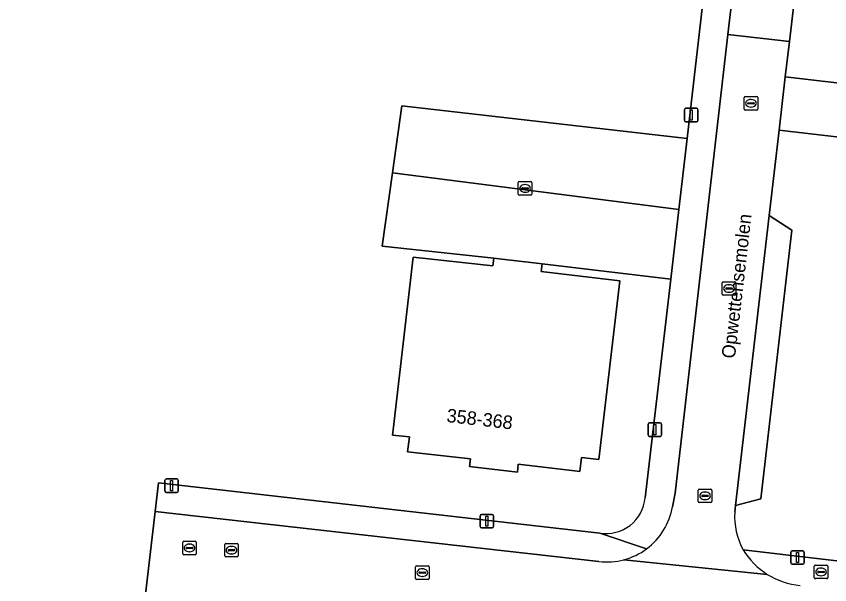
# Model space of a CAD drawing. Extents: x 161241 to 161758, y 384138 to 384885.
# Drawn here: x 161339.7 to 161399.9, y 384579.4 to 384621.5 of the extents above; entities that cross this region are included whole.
import ezdxf

# ---------------------------------------------------------------- set-up
doc = ezdxf.new("R2010")
doc.units = 0
for name, color, linetype in [('IMGEO_Brandkraan', 7, 'Continuous'), ('IMGEO_Erf', 7, 'Continuous'), ('IMGEO_Kolk', 7, 'Continuous'), ('IMGEO_Lichtmast', 7, 'Continuous'), ('IMGEO_Openbare_ruimte_label', 7, 'Continuous'), ('IMGEO_Pand', 7, 'Continuous'), ('IMGEO_Pand_nummerreeks', 7, 'Continuous'), ('IMGEO_Parkeervlak_open', 7, 'Continuous'), ('IMGEO_Rijbaan_lokaal_open', 7, 'Continuous'), ('IMGEO_Rioolput', 7, 'Continuous'), ('IMGEO_Voetpad_open', 7, 'Continuous')]:
    doc.layers.add(name, color=color, linetype=linetype)

msp = doc.modelspace()

# ---------------------------------------------------------------- linework, layer by layer
at = {"layer": 'IMGEO_Brandkraan'}
for p, q in [((161398.807, 384579.905), (161398.807, 384580.757)), ((161398.882, 384580.831), (161399.734, 384580.831)), ((161399.295, 384580.611), (161399.32, 384580.611)), ((161399.808, 384580.757), (161399.808, 384579.905)), ((161399.066, 384580.325), (161399.066, 384580.337)), ((161399.504, 384580.288), (161399.106, 384580.288)), ((161399.109, 384580.374), (161399.507, 384580.374)), ((161399.318, 384580.051), (161399.293, 384580.051)), ((161399.55, 384580.337), (161399.55, 384580.325)), ((161399.734, 384579.831), (161398.882, 384579.831))]:
    msp.add_line(p, q, dxfattribs=at)
for points in [[(161398.807, 384579.905), (161398.807, 384580.757)], [(161398.882, 384580.831), (161399.734, 384580.831)], [(161399.808, 384580.757), (161399.808, 384579.905)], [(161399.734, 384579.831), (161398.882, 384579.831)]]:
    msp.add_lwpolyline(points, dxfattribs=at)
for centre, radius, start, end in [((161398.884, 384580.755), 0.0765, 91.55205, 178.44795), ((161398.884, 384580.755), 0.0765, 91.55205, 178.44795), ((161399.732, 384580.755), 0.0765, 1.55205, 88.44795), ((161399.732, 384580.755), 0.0765, 1.55205, 88.44795), ((161399.106, 384580.334), 0.0403, 85.87752, 175.75265), ((161399.103, 384580.324), 0.0366, 178.93798, 274.71019), ((161399.507, 384580.331), 0.043, 264.86636, 352.45326), ((161399.511, 384580.336), 0.0386, 1.73085, 96.63898), ((161398.884, 384579.907), 0.0765, 181.55205, 268.44795), ((161398.884, 384579.907), 0.0765, 181.55205, 268.44795), ((161399.732, 384579.907), 0.0765, 271.55205, 358.44795), ((161399.732, 384579.907), 0.0765, 271.55205, 358.44795)]:
    msp.add_arc(centre, radius, start, end, dxfattribs=at)
for centre, major_axis, ratio, start_param, end_param in [((161399.294, 384580.331), (-0.387, 0.002), 0.722429, 4.712389, 7.853982), ((161399.319, 384580.331), (-0.39, 0.002), 0.717154, 1.570796, 4.712389)]:
    msp.add_ellipse(centre, major_axis=major_axis, ratio=ratio, start_param=start_param, end_param=end_param, dxfattribs=at)
at = {"layer": 'IMGEO_Erf'}
for points in [[(161458.589, 384639.718), (161400.088, 384646.416), (161397.281, 384622.401), (161396.961, 384619.66), (161396.655, 384617.039), (161425.024, 384613.724), (161425.387, 384616.773), (161427.698, 384616.498), (161427.335, 384613.449), (161436.939, 384612.308), (161436.503, 384609.048), (161435.624, 384602.469), (161435.067, 384598.3), (161434.079, 384598.432), (161434.571, 384602.594), (161430.726, 384603.048), (161431.421, 384608.981), (161396.194, 384613.099), (161395.453, 384606.759), (161397.13, 384605.671), (161394.834, 384585.76), (161392.961, 384585.251), (161392.905, 384584.764)], [(161386.264, 384585.815), (161388.17, 384602.03), (161378.63, 384603.18), (161378.553, 384602.616), (161384.384, 384601.913), (161382.88, 384589.077), (161382.832, 384588.671), (161381.561, 384588.828), (161381.438, 384587.782), (161381.025, 384587.83), (161376.862, 384588.317), (161376.812, 384587.738), (161373.26, 384588.138), (161373.333, 384588.711), (161369.092, 384589.195), (161368.661, 384589.244), (161368.811, 384590.339), (161367.545, 384590.466), (161367.592, 384590.876), (161369.069, 384603.683), (161374.991, 384603.033), (161375.048, 384603.608), (161366.788, 384604.482), (161367.54, 384609.919), (161368.227, 384614.894), (161389.377, 384612.476), (161392.602, 384640.347)], [(161332.131, 384432.245), (161332.897, 384438.907), (161336.632, 384471.394), (161336.946, 384474.139), (161340.403, 384504.377), (161340.647, 384506.515), (161340.82, 384506.489), (161349.943, 384584.816), (161350.191, 384586.943), (161382.92, 384583.217)], [(161393.526, 384581.977), (161448.824, 384575.465)]]:
    msp.add_lwpolyline(points, dxfattribs=at)
for centre, radius, start, end in [((161383.388, 384586.066), 2.887, 260.67579, 355.01247), ((161398.109, 384584.461), 5.213, 176.66706, 208.45585)]:
    msp.add_arc(centre, radius, start, end, dxfattribs=at)
at = {"layer": 'IMGEO_Kolk'}
for p, q in [((161393.684, 384615.584), (161394.536, 384615.584)), ((161393.609, 384614.658), (161393.609, 384615.51)), ((161393.868, 384615.078), (161393.868, 384615.09)), ((161394.306, 384615.041), (161393.908, 384615.041)), ((161393.911, 384615.127), (161394.309, 384615.127)), ((161394.097, 384615.364), (161394.122, 384615.364)), ((161394.352, 384615.09), (161394.352, 384615.078)), ((161394.61, 384615.51), (161394.61, 384614.658)), ((161394.536, 384614.584), (161393.684, 384614.584)), ((161394.12, 384614.804), (161394.095, 384614.804)), ((161376.869, 384608.348), (161376.869, 384609.2)), ((161376.944, 384609.274), (161377.796, 384609.274)), ((161377.357, 384609.054), (161377.382, 384609.054)), ((161377.87, 384609.2), (161377.87, 384608.348)), ((161377.128, 384608.768), (161377.128, 384608.78)), ((161377.566, 384608.731), (161377.168, 384608.731)), ((161377.171, 384608.817), (161377.569, 384608.817)), ((161377.38, 384608.494), (161377.355, 384608.494)), ((161377.612, 384608.78), (161377.612, 384608.768)), ((161377.796, 384608.274), (161376.944, 384608.274)), ((161391.987, 384600.926), (161391.987, 384601.778)), ((161392.062, 384601.852), (161392.914, 384601.852)), ((161392.988, 384601.778), (161392.988, 384600.926)), ((161392.246, 384601.346), (161392.246, 384601.358)), ((161392.684, 384601.309), (161392.286, 384601.309)), ((161392.289, 384601.395), (161392.687, 384601.395)), ((161392.475, 384601.632), (161392.5, 384601.632)), ((161392.73, 384601.358), (161392.73, 384601.346)), ((161392.914, 384600.852), (161392.062, 384600.852)), ((161392.498, 384601.072), (161392.473, 384601.072)), ((161390.209, 384585.55), (161390.209, 384586.402)), ((161390.284, 384586.476), (161391.136, 384586.476)), ((161390.697, 384586.256), (161390.722, 384586.256)), ((161391.21, 384586.402), (161391.21, 384585.55)), ((161391.136, 384585.476), (161390.284, 384585.476)), ((161390.468, 384585.97), (161390.468, 384585.982)), ((161390.906, 384585.933), (161390.508, 384585.933)), ((161390.511, 384586.019), (161390.909, 384586.019)), ((161390.72, 384585.696), (161390.695, 384585.696)), ((161390.952, 384585.982), (161390.952, 384585.97)), ((161355.187, 384582.444), (161356.039, 384582.444)), ((161355.112, 384581.518), (161355.112, 384582.37)), ((161355.371, 384581.938), (161355.371, 384581.95)), ((161355.809, 384581.901), (161355.411, 384581.901)), ((161355.414, 384581.987), (161355.812, 384581.987)), ((161355.6, 384582.224), (161355.625, 384582.224)), ((161355.855, 384581.95), (161355.855, 384581.938)), ((161356.113, 384582.37), (161356.113, 384581.518)), ((161356.039, 384581.444), (161355.187, 384581.444)), ((161355.623, 384581.664), (161355.598, 384581.664)), ((161369.257, 384579.854), (161369.257, 384580.706)), ((161369.332, 384580.78), (161370.184, 384580.78)), ((161370.258, 384580.706), (161370.258, 384579.854)), ((161369.516, 384580.274), (161369.516, 384580.286)), ((161369.954, 384580.237), (161369.556, 384580.237)), ((161369.559, 384580.323), (161369.957, 384580.323)), ((161369.768, 384580), (161369.743, 384580)), ((161369.745, 384580.56), (161369.77, 384580.56)), ((161370, 384580.286), (161370, 384580.274)), ((161370.184, 384579.78), (161369.332, 384579.78))]:
    msp.add_line(p, q, dxfattribs=at)
for points in [[(161393.684, 384615.584), (161394.536, 384615.584)], [(161393.609, 384614.658), (161393.609, 384615.51)], [(161394.61, 384615.51), (161394.61, 384614.658)], [(161394.536, 384614.584), (161393.684, 384614.584)], [(161376.869, 384608.348), (161376.869, 384609.2)], [(161376.944, 384609.274), (161377.796, 384609.274)], [(161377.87, 384609.2), (161377.87, 384608.348)], [(161377.796, 384608.274), (161376.944, 384608.274)], [(161391.987, 384600.926), (161391.987, 384601.778)], [(161392.062, 384601.852), (161392.914, 384601.852)], [(161392.988, 384601.778), (161392.988, 384600.926)], [(161392.914, 384600.852), (161392.062, 384600.852)], [(161390.209, 384585.55), (161390.209, 384586.402)], [(161390.284, 384586.476), (161391.136, 384586.476)], [(161391.21, 384586.402), (161391.21, 384585.55)], [(161391.136, 384585.476), (161390.284, 384585.476)], [(161355.187, 384582.444), (161356.039, 384582.444)], [(161355.112, 384581.518), (161355.112, 384582.37)], [(161356.113, 384582.37), (161356.113, 384581.518)], [(161356.039, 384581.444), (161355.187, 384581.444)], [(161369.257, 384579.854), (161369.257, 384580.706)], [(161369.332, 384580.78), (161370.184, 384580.78)], [(161370.258, 384580.706), (161370.258, 384579.854)], [(161370.184, 384579.78), (161369.332, 384579.78)]]:
    msp.add_lwpolyline(points, dxfattribs=at)
for centre, radius, start, end in [((161393.686, 384615.508), 0.0765, 91.55205, 178.44795), ((161393.686, 384615.508), 0.0765, 91.55205, 178.44795), ((161394.534, 384615.508), 0.0765, 1.55205, 88.44795), ((161394.534, 384615.508), 0.0765, 1.55205, 88.44795), ((161393.908, 384615.087), 0.0403, 85.87752, 175.75265), ((161393.905, 384615.077), 0.0366, 178.93798, 274.71019), ((161394.309, 384615.084), 0.043, 264.86636, 352.45326), ((161394.313, 384615.089), 0.0386, 1.73085, 96.63898), ((161393.686, 384614.66), 0.0765, 181.55205, 268.44795), ((161393.686, 384614.66), 0.0765, 181.55205, 268.44795), ((161394.534, 384614.66), 0.0765, 271.55205, 358.44795), ((161394.534, 384614.66), 0.0765, 271.55205, 358.44795), ((161376.946, 384609.198), 0.0765, 91.55205, 178.44795), ((161376.946, 384609.198), 0.0765, 91.55205, 178.44795), ((161377.794, 384609.198), 0.0765, 1.55205, 88.44795), ((161377.794, 384609.198), 0.0765, 1.55205, 88.44795), ((161376.946, 384608.35), 0.0765, 181.55205, 268.44795), ((161376.946, 384608.35), 0.0765, 181.55205, 268.44795), ((161377.168, 384608.777), 0.0403, 85.87752, 175.75265), ((161377.165, 384608.767), 0.0366, 178.93798, 274.71019), ((161377.569, 384608.774), 0.043, 264.86636, 352.45326), ((161377.573, 384608.779), 0.0386, 1.73085, 96.63898), ((161377.794, 384608.35), 0.0765, 271.55205, 358.44795), ((161377.794, 384608.35), 0.0765, 271.55205, 358.44795), ((161392.064, 384601.776), 0.0765, 91.55205, 178.44795), ((161392.064, 384601.776), 0.0765, 91.55205, 178.44795), ((161392.912, 384601.776), 0.0765, 1.55205, 88.44795), ((161392.912, 384601.776), 0.0765, 1.55205, 88.44795), ((161392.286, 384601.355), 0.0403, 85.87752, 175.75265), ((161392.283, 384601.345), 0.0366, 178.93798, 274.71019), ((161392.687, 384601.352), 0.043, 264.86636, 352.45326), ((161392.691, 384601.357), 0.0386, 1.73085, 96.63898), ((161392.064, 384600.928), 0.0765, 181.55205, 268.44795), ((161392.064, 384600.928), 0.0765, 181.55205, 268.44795), ((161392.912, 384600.928), 0.0765, 271.55205, 358.44795), ((161392.912, 384600.928), 0.0765, 271.55205, 358.44795), ((161390.286, 384586.4), 0.0765, 91.55205, 178.44795), ((161390.286, 384586.4), 0.0765, 91.55205, 178.44795), ((161391.134, 384586.4), 0.0765, 1.55205, 88.44795), ((161391.134, 384586.4), 0.0765, 1.55205, 88.44795), ((161390.286, 384585.552), 0.0765, 181.55205, 268.44795), ((161390.286, 384585.552), 0.0765, 181.55205, 268.44795), ((161390.508, 384585.979), 0.0403, 85.87752, 175.75265), ((161390.505, 384585.969), 0.0366, 178.93798, 274.71019), ((161390.909, 384585.976), 0.043, 264.86636, 352.45326), ((161390.913, 384585.981), 0.0386, 1.73085, 96.63898), ((161391.134, 384585.552), 0.0765, 271.55205, 358.44795), ((161391.134, 384585.552), 0.0765, 271.55205, 358.44795), ((161355.189, 384582.368), 0.0765, 91.55205, 178.44795), ((161355.189, 384582.368), 0.0765, 91.55205, 178.44795), ((161356.037, 384582.368), 0.0765, 1.55205, 88.44795), ((161356.037, 384582.368), 0.0765, 1.55205, 88.44795), ((161355.411, 384581.947), 0.0403, 85.87752, 175.75265), ((161355.408, 384581.937), 0.0366, 178.93798, 274.71019), ((161355.812, 384581.944), 0.043, 264.86636, 352.45326), ((161355.816, 384581.949), 0.0386, 1.73085, 96.63898), ((161355.189, 384581.52), 0.0765, 181.55205, 268.44795), ((161355.189, 384581.52), 0.0765, 181.55205, 268.44795), ((161356.037, 384581.52), 0.0765, 271.55205, 358.44795), ((161356.037, 384581.52), 0.0765, 271.55205, 358.44795), ((161369.334, 384580.704), 0.0765, 91.55205, 178.44795), ((161369.334, 384580.704), 0.0765, 91.55205, 178.44795), ((161370.182, 384580.704), 0.0765, 1.55205, 88.44795), ((161370.182, 384580.704), 0.0765, 1.55205, 88.44795), ((161369.556, 384580.283), 0.0403, 85.87752, 175.75265), ((161369.553, 384580.273), 0.0366, 178.93798, 274.71019), ((161369.957, 384580.28), 0.043, 264.86636, 352.45326), ((161369.961, 384580.285), 0.0386, 1.73085, 96.63898), ((161369.334, 384579.856), 0.0765, 181.55205, 268.44795), ((161369.334, 384579.856), 0.0765, 181.55205, 268.44795), ((161370.182, 384579.856), 0.0765, 271.55205, 358.44795), ((161370.182, 384579.856), 0.0765, 271.55205, 358.44795)]:
    msp.add_arc(centre, radius, start, end, dxfattribs=at)
for centre, major_axis, ratio, start_param, end_param in [((161394.096, 384615.084), (-0.387, 0.002), 0.722429, 4.712389, 7.853982), ((161394.121, 384615.084), (-0.39, 0.002), 0.717154, 1.570796, 4.712389), ((161377.356, 384608.774), (-0.387, 0.002), 0.722429, 4.712389, 7.853982), ((161377.381, 384608.774), (-0.39, 0.002), 0.717154, 1.570796, 4.712389), ((161392.474, 384601.352), (-0.387, 0.002), 0.722429, 4.712389, 7.853982), ((161392.499, 384601.352), (-0.39, 0.002), 0.717154, 1.570796, 4.712389), ((161390.696, 384585.976), (-0.387, 0.002), 0.722429, 4.712389, 7.853982), ((161390.721, 384585.976), (-0.39, 0.002), 0.717154, 1.570796, 4.712389), ((161355.599, 384581.944), (-0.387, 0.002), 0.722429, 4.712389, 7.853982), ((161355.624, 384581.944), (-0.39, 0.002), 0.717154, 1.570796, 4.712389), ((161369.744, 384580.28), (-0.387, 0.002), 0.722429, 4.712389, 7.853982), ((161369.769, 384580.28), (-0.39, 0.002), 0.717154, 1.570796, 4.712389)]:
    msp.add_ellipse(centre, major_axis=major_axis, ratio=ratio, start_param=start_param, end_param=end_param, dxfattribs=at)
at = {"layer": 'IMGEO_Lichtmast'}
for p, q in [((161389.186, 384613.816), (161389.186, 384614.616)), ((161389.186, 384614.616), (161389.186, 384613.816)), ((161389.286, 384614.716), (161390.076, 384614.716)), ((161390.076, 384614.716), (161389.286, 384614.716)), ((161390.176, 384614.616), (161390.176, 384613.816)), ((161390.176, 384613.816), (161390.176, 384614.616)), ((161390.076, 384613.716), (161389.286, 384613.716)), ((161389.286, 384613.716), (161390.076, 384613.716)), ((161386.486, 384590.483), (161386.486, 384591.283)), ((161386.486, 384591.283), (161386.486, 384590.483)), ((161386.586, 384591.383), (161387.376, 384591.383)), ((161387.376, 384591.383), (161386.586, 384591.383)), ((161387.476, 384591.283), (161387.476, 384590.483)), ((161387.476, 384590.483), (161387.476, 384591.283)), ((161387.376, 384590.383), (161386.586, 384590.383)), ((161386.586, 384590.383), (161387.376, 384590.383)), ((161350.681, 384586.324), (161350.681, 384587.124)), ((161350.681, 384587.124), (161350.681, 384586.324)), ((161350.781, 384587.224), (161351.571, 384587.224)), ((161351.571, 384587.224), (161350.781, 384587.224)), ((161351.671, 384587.124), (161351.671, 384586.324)), ((161351.671, 384586.324), (161351.671, 384587.124)), ((161351.571, 384586.224), (161350.781, 384586.224)), ((161350.781, 384586.224), (161351.571, 384586.224)), ((161374.036, 384583.695), (161374.036, 384584.495)), ((161374.036, 384584.495), (161374.036, 384583.695)), ((161374.136, 384584.595), (161374.926, 384584.595)), ((161374.926, 384584.595), (161374.136, 384584.595)), ((161375.026, 384584.495), (161375.026, 384583.695)), ((161375.026, 384583.695), (161375.026, 384584.495)), ((161374.926, 384583.595), (161374.136, 384583.595)), ((161374.136, 384583.595), (161374.926, 384583.595)), ((161397.159, 384581.903), (161397.949, 384581.903)), ((161397.949, 384581.903), (161397.159, 384581.903)), ((161397.059, 384581.003), (161397.059, 384581.803)), ((161397.059, 384581.803), (161397.059, 384581.003)), ((161398.049, 384581.803), (161398.049, 384581.003)), ((161398.049, 384581.003), (161398.049, 384581.803)), ((161397.949, 384580.903), (161397.159, 384580.903)), ((161397.159, 384580.903), (161397.949, 384580.903))]:
    msp.add_line(p, q, dxfattribs=at)
for points in [[(161389.606, 384614.591), (161389.756, 384614.591), (161389.756, 384613.841), (161389.606, 384613.841), (161389.606, 384614.591)], [(161386.906, 384591.258), (161387.056, 384591.258), (161387.056, 384590.508), (161386.906, 384590.508), (161386.906, 384591.258)], [(161351.101, 384587.099), (161351.251, 384587.099), (161351.251, 384586.349), (161351.101, 384586.349), (161351.101, 384587.099)], [(161374.456, 384584.47), (161374.606, 384584.47), (161374.606, 384583.72), (161374.456, 384583.72), (161374.456, 384584.47)], [(161397.479, 384581.778), (161397.629, 384581.778), (161397.629, 384581.028), (161397.479, 384581.028), (161397.479, 384581.778)]]:
    msp.add_lwpolyline(points, dxfattribs=at)
for centre, start, end in [((161389.286, 384614.616), 90, 180), ((161389.286, 384614.616), 90, 180), ((161390.076, 384614.616), 0, 90), ((161390.076, 384614.616), 360, 90), ((161389.286, 384613.816), 180, 270), ((161389.286, 384613.816), 180, 270), ((161390.076, 384613.816), 270, 0), ((161390.076, 384613.816), 270, 0), ((161386.586, 384591.283), 90, 180), ((161386.586, 384591.283), 90, 180), ((161387.376, 384591.283), 0, 90), ((161387.376, 384591.283), 360, 90), ((161386.586, 384590.483), 180, 270), ((161386.586, 384590.483), 180, 270), ((161387.376, 384590.483), 270, 0), ((161387.376, 384590.483), 270, 0), ((161350.781, 384587.124), 90, 180), ((161350.781, 384587.124), 90, 180), ((161351.571, 384587.124), 0, 90), ((161351.571, 384587.124), 360, 90), ((161350.781, 384586.324), 180, 270), ((161350.781, 384586.324), 180, 270), ((161351.571, 384586.324), 270, 0), ((161351.571, 384586.324), 270, 0), ((161374.136, 384584.495), 90, 180), ((161374.136, 384584.495), 90, 180), ((161374.926, 384584.495), 0, 90), ((161374.926, 384584.495), 360, 90), ((161374.136, 384583.695), 180, 270), ((161374.136, 384583.695), 180, 270), ((161374.926, 384583.695), 270, 0), ((161374.926, 384583.695), 270, 0), ((161397.159, 384581.803), 90, 180), ((161397.159, 384581.803), 90, 180), ((161397.949, 384581.803), 0, 90), ((161397.949, 384581.803), 360, 90), ((161397.159, 384581.003), 180, 270), ((161397.159, 384581.003), 180, 270), ((161397.949, 384581.003), 270, 0), ((161397.949, 384581.003), 270, 0)]:
    msp.add_arc(centre, 0.1, start, end, dxfattribs=at)
at = {"layer": 'IMGEO_Pand'}
msp.add_lwpolyline([(161381.025, 384587.83), (161381.438, 384587.782), (161381.561, 384588.828), (161382.832, 384588.671), (161382.88, 384589.077), (161384.384, 384601.913), (161378.553, 384602.616), (161378.63, 384603.18), (161378.018, 384603.253), (161375.64, 384603.537), (161375.048, 384603.608), (161374.991, 384603.033), (161369.069, 384603.683), (161367.592, 384590.876), (161367.545, 384590.466), (161368.811, 384590.339), (161368.661, 384589.244), (161369.092, 384589.195), (161373.333, 384588.711), (161373.26, 384588.138), (161376.812, 384587.738), (161376.862, 384588.317)], close=True, dxfattribs=at)
at = {"layer": 'IMGEO_Parkeervlak_open'}
for points in [[(161389.377, 384612.476), (161368.227, 384614.894), (161367.54, 384609.919), (161388.77, 384607.218)], [(161392.961, 384585.251), (161394.834, 384585.76), (161397.13, 384605.671), (161395.453, 384606.759)]]:
    msp.add_lwpolyline(points, close=True, dxfattribs=at)
at = {"layer": 'IMGEO_Rijbaan_lokaal_open'}
for points in [[(161396.961, 384619.66), (161397.281, 384622.401), (161392.722, 384622.926), (161392.406, 384620.184)], [(161436.939, 384612.308), (161427.335, 384613.449), (161426.205, 384613.584), (161425.024, 384613.724), (161396.655, 384617.039), (161396.194, 384613.099), (161431.421, 384608.981), (161430.726, 384603.048), (161434.571, 384602.594), (161435.624, 384602.469), (161436.503, 384609.048)], [(161388.77, 384607.218), (161367.54, 384609.919), (161366.788, 384604.482), (161375.048, 384603.608), (161375.64, 384603.537), (161378.018, 384603.253), (161378.63, 384603.18), (161388.17, 384602.03)]]:
    msp.add_lwpolyline(points, close=True, dxfattribs=at)
for points in [[(161395.453, 384606.759), (161396.194, 384613.099), (161396.655, 384617.039), (161396.961, 384619.66), (161392.406, 384620.184), (161388.487, 384586.169), (161388.291, 384585.165)], [(161392.905, 384584.764), (161392.961, 384585.251), (161395.453, 384606.759)], [(161382.841, 384581.101), (161349.943, 384584.816), (161340.82, 384506.489), (161354.376, 384504.9), (161354.929, 384509.609), (161349.844, 384510.209)], [(161395.321, 384580.15), (161384.7, 384581.234)], [(161384.7, 384581.234), (161395.321, 384580.15)]]:
    msp.add_lwpolyline(points, dxfattribs=at)
for centre, radius, start, end in [((161383.427, 384586.003), 4.936, 306.7053, 350.22329), ((161398.109, 384584.461), 5.213, 176.66706, 208.45585), ((161383.428, 384585.999), 4.932, 284.94869, 306.72366), ((161398.291, 384584.863), 5.57, 211.20257, 237.78505), ((161383.424, 384586.004), 4.937, 263.21297, 284.97141), ((161398.286, 384584.86), 5.565, 237.81251, 264.42645)]:
    msp.add_arc(centre, radius, start, end, dxfattribs=at)
at = {"layer": 'IMGEO_Rioolput'}
for p, q in [((161352, 384581.682), (161352, 384582.534)), ((161352.075, 384582.608), (161352.927, 384582.608)), ((161353.001, 384582.534), (161353.001, 384581.682)), ((161352.259, 384582.102), (161352.259, 384582.114)), ((161352.697, 384582.065), (161352.299, 384582.065)), ((161352.302, 384582.151), (161352.7, 384582.151)), ((161352.511, 384581.828), (161352.486, 384581.828)), ((161352.488, 384582.388), (161352.513, 384582.388)), ((161352.743, 384582.114), (161352.743, 384582.102)), ((161352.927, 384581.608), (161352.075, 384581.608))]:
    msp.add_line(p, q, dxfattribs=at)
for points in [[(161352, 384581.682), (161352, 384582.534)], [(161352.075, 384582.608), (161352.927, 384582.608)], [(161353.001, 384582.534), (161353.001, 384581.682)], [(161352.927, 384581.608), (161352.075, 384581.608)]]:
    msp.add_lwpolyline(points, dxfattribs=at)
for centre, radius, start, end in [((161352.077, 384582.532), 0.0765, 91.55205, 178.44795), ((161352.077, 384582.532), 0.0765, 91.55205, 178.44795), ((161352.925, 384582.532), 0.0765, 1.55205, 88.44795), ((161352.925, 384582.532), 0.0765, 1.55205, 88.44795), ((161352.299, 384582.111), 0.0403, 85.87752, 175.75265), ((161352.296, 384582.101), 0.0366, 178.93798, 274.71019), ((161352.7, 384582.108), 0.043, 264.86636, 352.45326), ((161352.704, 384582.113), 0.0386, 1.73085, 96.63898), ((161352.077, 384581.684), 0.0765, 181.55205, 268.44795), ((161352.077, 384581.684), 0.0765, 181.55205, 268.44795), ((161352.925, 384581.684), 0.0765, 271.55205, 358.44795), ((161352.925, 384581.684), 0.0765, 271.55205, 358.44795)]:
    msp.add_arc(centre, radius, start, end, dxfattribs=at)
for centre, major_axis, ratio, start_param, end_param in [((161352.487, 384582.108), (-0.387, 0.002), 0.722429, 4.712389, 7.853982), ((161352.512, 384582.108), (-0.39, 0.002), 0.717154, 1.570796, 4.712389)]:
    msp.add_ellipse(centre, major_axis=major_axis, ratio=ratio, start_param=start_param, end_param=end_param, dxfattribs=at)
at = {"layer": 'IMGEO_Voetpad_open'}
for points in [[(161392.602, 384640.347), (161389.377, 384612.476), (161388.77, 384607.218), (161388.17, 384602.03), (161386.264, 384585.815)], [(161388.291, 384585.165), (161388.487, 384586.169), (161392.406, 384620.184), (161392.722, 384622.926)], [(161350.191, 384586.943), (161349.943, 384584.816), (161382.841, 384581.101)], [(161386.377, 384582.046), (161382.92, 384583.217), (161350.191, 384586.943)], [(161382.92, 384583.217), (161386.377, 384582.046)], [(161448.824, 384575.465), (161393.526, 384581.977)]]:
    msp.add_lwpolyline(points, dxfattribs=at)
for centre, radius, start, end in [((161383.388, 384586.066), 2.887, 260.67579, 355.01247), ((161383.427, 384586.003), 4.936, 306.7053, 350.22329), ((161383.428, 384585.999), 4.932, 284.94869, 306.72366), ((161398.291, 384584.863), 5.57, 211.20257, 237.78505), ((161383.424, 384586.004), 4.937, 263.21297, 284.97141), ((161398.286, 384584.86), 5.565, 237.81251, 264.42645)]:
    msp.add_arc(centre, radius, start, end, dxfattribs=at)

# ---------------------------------------------------------------- texts
at = {"layer": 'IMGEO_Openbare_ruimte_label'}
msp.add_text('Opwettensemolen', height=1, rotation=83.33704, dxfattribs=at).set_placement((161392.915, 384596.118))
at = {"layer": 'IMGEO_Pand_nummerreeks'}
msp.add_text('358-368', height=1, rotation=353.47236, dxfattribs=at).set_placement((161371.515, 384591.454))

doc.saveas('drawing.dxf')
